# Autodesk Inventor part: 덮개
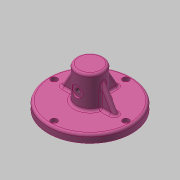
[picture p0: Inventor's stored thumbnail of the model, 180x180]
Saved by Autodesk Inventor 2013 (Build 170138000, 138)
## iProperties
Created: 2017-08
Part Number: 덮개
Material: 알루미늄 6061
Document SubType Name: Modeling
Designer: mduedu
Density: 2.71 g/cm^3
Mass: 336.254 g
Surface Area: 314.318 cm^2
Volume: 124.079 cm^3
Author: mduedu
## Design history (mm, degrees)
sketch "스케치1"
  geometry: C1 r 52.5 at (0, 0); 1 further point
  constraints: 1 centre point, 1 coincident
  dimensions: "d55" = 105 diameter of C1
extrude "돌출1" new body sketch "스케치1" distance "d5" = 10; taper "d6" = 0 deg
sketch "스케치2"
  geometry: C1 r 17 at (0, 0); 1 further point
  constraints: 1 centre point, 1 coincident
  dimensions: "d74" = 34 diameter of C1
extrude "돌출2" join sketch "스케치2" distance "d9" = 40; taper "d10" = 0 deg
sketch "스케치3"
  geometry: C1 r 37 at (0, 0); 1 further point
  constraints: 1 centre point, 1 coincident
  dimensions: "d56" = 74 diameter of C1
extrude "돌출3" join sketch "스케치3" distance "d12" = 8; taper "d13" = 0 deg
sketch "스케치4"
  geometry: C1 r 33 at (0, 0); 1 further point
  constraints: 1 centre point, 1 coincident
  dimensions: "d57" = 66 diameter of C1
extrude "돌출4" cut sketch "스케치4" distance "d16" = 7; taper "d17" = 0 deg
sketch "스케치5"
  geometry: C1 r 9 at (0, 0); 1 further point
  constraints: 1 centre point, 1 coincident
  dimensions: "d18" = 18 diameter of C1
extrude "돌출5" cut sketch "스케치5" distance "d19" = 47; taper "d20" = 0 deg
node "작업 평면1"
sketch "스케치11"
  geometry: L1 (-52.5, -10)-(52.5, -10) reference; 2 further points
  constraints: 1 vertical alignment
  dimensions: "d78" = 28 distance from line of point (0, 18) L1
hole "구멍5" sketch "스케치11" at (0, 18) diameter "d79" = 5.917; stored, may be unused: countersink angle "d83" = 90 deg, drill point angle "d85" = 118 deg; dims "d80" = 6, "d81" = 14, "d82" = 2, "d84" = 8
fillet "모깎기9" dims "d86" = 3
fillet "모깎기5" dims "d40" = 1
sketch "스케치12"
  geometry: C1 r 2.5 at (0, 0); 1 further point
  constraints: 1 centre point, 1 coincident
  dimensions: "d87" = 5 diameter of C1
extrude "돌출6" join sketch "스케치12" distance "d88" = 3; taper "d89" = 0 deg
fillet "모깎기10" dims "d91" = 1
chamfer "모따기1" distance "d41" = 1; stored, may be unused: second distance "d42" = 2, angle "d43" = 45 deg
fillet "모깎기7" dims "d45" = 3
fillet "모깎기8" dims "d46" = 3
sketch "스케치10" dims "d59" = 90
  geometry: 3 further points
  constraints: 2 vertical alignment, 1 coincident, 2 other
hole "구멍4" sketch "스케치10" at (0, 45) diameter "d60" = 4.5; stored, may be unused: countersink angle "d64" = 90 deg, drill point angle "d66" = 118 deg; dims "d61" = 6, "d62" = 8, "d63" = 4.6, "d65" = 8
sketch "스케치13"
  geometry: L1 (52.5, 7)-(52.5, 0) reference; L2 (52.5, 0)-(47.25, 0) reference; L3 (47.25, 0)-(47.25, 5.4) reference; L4 (47.25, 5.4)-(49, 5.4) reference; L5 (49, 5.4)-(49, 10) reference; L6 (49, 10)-(49.5, 10) reference; L7 (-49.5, 10)-(-49, 10) reference; L8 (-49, 10)-(-49, 5.4) reference; L9 (-49, 5.4)-(-47.25, 5.4) reference; L10 (-47.25, 5.4)-(-47.25, 0) reference; L11 (-47.25, 0)-(-52.5, 0) reference; L12 (-52.5, 0)-(-52.5, 7) reference; L13 (-3.5, 46)-(-8, 46) reference; L14 (-9, 45)-(-9, -1) reference; L15 (-9, -1)-(-30, -1) reference; L16 (-33, -4)-(-33, -8) reference; L17 (-33, -8)-(-36, -8) reference; L18 (-36, -8)-(-37, -7) reference; L19 (-37, -7)-(-37, 0) reference; L20 (-37, 0)-(-42.75, 0) reference; L21 (-42.75, 0)-(-42.75, 5.4) reference; L22 (-42.75, 5.4)-(-41, 5.4) reference; L23 (-41, 5.4)-(-41, 10) reference; L24 (-41, 10)-(-20, 10) reference; L25 (-17, 13)-(-17, 47) reference; L26 (-14, 50)-(14, 50) reference; L27 (17, 47)-(17, 13) reference; L28 (20, 10)-(41, 10) reference; L29 (41, 10)-(41, 5.4) reference; L30 (41, 5.4)-(42.75, 5.4) reference; L31 (42.75, 5.4)-(42.75, 0) reference; L32 (42.75, 0)-(37, 0) reference; L33 (37, 0)-(37, -7) reference; L34 (37, -7)-(36, -8) reference; L35 (36, -8)-(33, -8) reference; L36 (33, -8)-(33, -4) reference; L37 (30, -1)-(9, -1) reference; L38 (9, -1)-(9, 45) reference; L39 (8, 46)-(3.5, 46) reference; L40 (2.5, 45)-(2.5, 43) reference; L41 (2.5, 43)-(-2.5, 43) reference; L42 (-2.5, 43)-(-2.5, 45) reference; L43 (17, 40)-(34.321, 10); L44 (-49.5, 10)-(49.5, 10) reference; A1 r 3 centre (49.5, 7) between (52.5, 7) and (49.5, 10) reference; A2 r 3 centre (-49.5, 7) between (-49.5, 10) and (-52.5, 7) reference; A3 r 1 centre (-3.5, 45) between (-2.5, 45) and (-3.5, 46) reference; A4 r 1 centre (-8, 45) between (-8, 46) and (-9, 45) reference; A5 r 3 centre (-30, -4) between (-30, -1) and (-33, -4) reference; A6 r 3 centre (-20, 13) between (-20, 10) and (-17, 13) reference; A7 r 3 centre (-14, 47) between (-14, 50) and (-17, 47) reference; A8 r 3 centre (14, 47) between (17, 47) and (14, 50) reference; A9 r 3 centre (20, 13) between (17, 13) and (20, 10) reference; A10 r 3 centre (30, -4) between (33, -4) and (30, -1) reference; A11 r 1 centre (8, 45) between (9, 45) and (8, 46) reference; A12 r 1 centre (3.5, 45) between (3.5, 46) and (2.5, 45) reference; 1 further point
  constraints: 2 end point, 2 point on line
  dimensions: "d98" = 120 deg angle of L43 L28; "d99" = 30 distance from line of L43.start L44
feature "리브1" sketch "스케치13" dims "d100" = 1, "d101" = 6, "d102" = 0, "d103" = 0, "d104" = 1, "d105" = 1
fillet "모깎기11" dims "d106" = 3
fillet "모깎기12" dims "d107" = 3
node "솔리드1"
pattern_circular "원형 패턴1" dims angle "d68" = 360 deg
pattern_circular "원형 패턴2" dims "d109" = 270 deg
node "절단 모서리 투영1"
